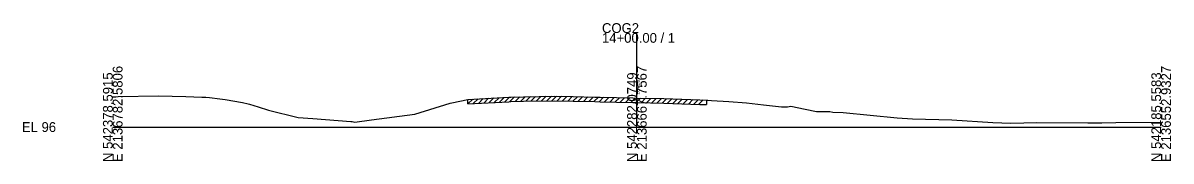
# Model space of a CAD drawing. Extents: x -13397 to 2303, y -10 to 39059.
# Drawn here: x -25.7 to 302.8, y 7990.3 to 8029.7 of the extents above; entities that cross this region are included whole.
import ezdxf

# ---------------------------------------------------------------- set-up
doc = ezdxf.new("R2010")
doc.units = 0
for name, color, linetype in [('RD_GPK_XS_Cell', 7, 'Continuous'), ('RD_XS_ExGround', 7, 'Continuous'), ('RD_XS_ExPaveRet', 7, 'Continuous'), ('RD_XS_TX_Elev_EX', 7, 'Continuous')]:
    doc.layers.add(name, color=color, linetype=linetype)

msp = doc.modelspace()

# ---------------------------------------------------------------- linework, layer by layer
at = {"layer": 'RD_GPK_XS_Cell'}
for p, q in [((150, 8000), (150, 8026.87)), ((0, 8000), (150, 8000)), ((150, 8000), (300, 8000))]:
    msp.add_line(p, q, dxfattribs=at)
at = {"layer": 'RD_XS_ExGround'}
for p, q in [((0, 8008.64), (0.86, 8008.67)), ((0.86, 8008.67), (1.51, 8008.68)), ((1.51, 8008.68), (13.13, 8008.96)), ((13.13, 8008.96), (20.96, 8008.7)), ((20.96, 8008.7), (25.51, 8008.54)), ((25.51, 8008.54), (26.68, 8008.5)), ((26.68, 8008.5), (27.7, 8008.46)), ((27.7, 8008.46), (30.66, 8008.02)), ((30.66, 8008.02), (32.19, 8007.84)), ((32.19, 8007.84), (37.13, 8007.03)), ((37.13, 8007.03), (38.78, 8006.62)), ((38.78, 8006.62), (39.1, 8006.5)), ((39.1, 8006.5), (41.59, 8005.73)), ((86.49, 8003.68), (96.57, 8006.78)), ((96.57, 8006.78), (97.08, 8006.91)), ((97.08, 8006.91), (101.65, 8007.91)), ((101.65, 8007.91), (113.36, 8008.55)), ((113.36, 8008.55), (113.91, 8008.58)), ((113.91, 8008.58), (117.5, 8008.65)), ((117.5, 8008.65), (126.4, 8008.83)), ((126.4, 8008.83), (131.72, 8008.7)), ((131.72, 8008.7), (137.99, 8008.56)), ((137.99, 8008.56), (139.49, 8008.51)), ((139.49, 8008.51), (148.84, 8008.3)), ((148.84, 8008.3), (150, 8008.28)), ((150, 8008.28), (157.72, 8008.11)), ((157.72, 8008.11), (168.02, 8007.78)), ((168.02, 8007.78), (169.9, 8007.71)), ((169.9, 8007.71), (170.3, 8007.7)), ((170.3, 8007.7), (171.37, 8007.61)), ((171.37, 8007.61), (176.34, 8007.27)), ((176.34, 8007.27), (181.37, 8006.96)), ((181.37, 8006.96), (186.19, 8006.39)), ((186.19, 8006.39), (191.37, 8005.78)), ((41.59, 8005.73), (44.61, 8004.79)), ((44.61, 8004.79), (53.09, 8002.77)), ((74.02, 8002.1), (86.49, 8003.68)), ((191.37, 8005.78), (193.05, 8005.81)), ((193.05, 8005.81), (194.03, 8005.94)), ((194.03, 8005.94), (198.12, 8005.09)), ((198.12, 8005.09), (201.38, 8004.4)), ((201.38, 8004.4), (203.09, 8004.48)), ((203.09, 8004.48), (205.16, 8004.4)), ((205.16, 8004.4), (206.06, 8004.25)), ((206.06, 8004.25), (209, 8004.13)), ((209, 8004.13), (224.45, 8002.59)), ((53.09, 8002.77), (57.25, 8002.46)), ((57.25, 8002.46), (68.14, 8001.62)), ((68.14, 8001.62), (68.5, 8001.56)), ((68.5, 8001.56), (69.28, 8001.44)), ((69.28, 8001.44), (74.02, 8002.1)), ((224.45, 8002.59), (228.85, 8002.36)), ((228.85, 8002.36), (240.11, 8002.07)), ((240.11, 8002.07), (251.86, 8001.32)), ((251.86, 8001.32), (254.45, 8001.18)), ((254.45, 8001.18), (257.01, 8001.15)), ((257.01, 8001.15), (264.45, 8001.28)), ((264.45, 8001.28), (279.02, 8001.19)), ((279.02, 8001.19), (283.08, 8001.21)), ((283.08, 8001.21), (287, 8001.27)), ((287, 8001.27), (300, 8001.41))]:
    msp.add_line(p, q, dxfattribs=at)
at = {"layer": 'RD_XS_ExPaveRet'}
for p, q in [((101.65, 8006.61), (103.03, 8007.98)), ((101.65, 8006.61), (101.65, 8007.91)), ((101.65, 8006.61), (113.36, 8007.25)), ((103.16, 8006.69), (104.53, 8008.07)), ((104.66, 8006.77), (106.03, 8008.15)), ((106.16, 8006.85), (107.54, 8008.23)), ((107.66, 8006.94), (109.04, 8008.31)), ((109.16, 8007.02), (110.54, 8008.39)), ((110.66, 8007.1), (112.04, 8008.47)), ((112.17, 8007.18), (113.54, 8008.56)), ((113.36, 8007.25), (113.91, 8007.28)), ((113.67, 8007.27), (115.01, 8008.6)), ((113.91, 8007.28), (117.5, 8007.35)), ((115.17, 8007.3), (116.5, 8008.63)), ((116.67, 8007.33), (118, 8008.66)), ((117.5, 8007.35), (126.4, 8007.53)), ((118.17, 8007.36), (119.5, 8008.69)), ((119.68, 8007.39), (121, 8008.72)), ((121.18, 8007.42), (122.51, 8008.75)), ((122.68, 8007.45), (124.01, 8008.78)), ((124.18, 8007.48), (125.51, 8008.81)), ((125.68, 8007.51), (126.99, 8008.81)), ((126.4, 8007.53), (131.72, 8007.4)), ((127.19, 8007.51), (128.46, 8008.78)), ((128.69, 8007.47), (129.96, 8008.74)), ((130.19, 8007.44), (131.46, 8008.71)), ((131.69, 8007.4), (132.96, 8008.67)), ((131.72, 8007.4), (137.99, 8007.26)), ((133.19, 8007.37), (134.47, 8008.64)), ((134.7, 8007.33), (135.97, 8008.6)), ((136.2, 8007.3), (137.47, 8008.57)), ((137.7, 8007.26), (138.97, 8008.53)), ((137.99, 8007.26), (139.49, 8007.21)), ((139.2, 8007.22), (140.47, 8008.49)), ((139.49, 8007.21), (148.84, 8007)), ((140.7, 8007.19), (141.98, 8008.46)), ((142.21, 8007.15), (143.48, 8008.42)), ((143.71, 8007.12), (144.98, 8008.39)), ((145.21, 8007.08), (146.48, 8008.35)), ((146.71, 8007.05), (147.98, 8008.32)), ((148.21, 8007.02), (149.49, 8008.29)), ((148.84, 8007), (150, 8006.98)), ((149.71, 8006.98), (150.99, 8008.26)), ((150, 8006.98), (157.72, 8006.81)), ((151.22, 8006.95), (152.49, 8008.22)), ((152.72, 8006.92), (153.99, 8008.19)), ((154.22, 8006.89), (155.5, 8008.16)), ((155.72, 8006.86), (157, 8008.13)), ((157.22, 8006.83), (158.49, 8008.09)), ((157.72, 8006.81), (168.02, 8006.48)), ((158.73, 8006.78), (159.99, 8008.04)), ((160.23, 8006.73), (161.49, 8007.99)), ((161.73, 8006.68), (162.99, 8007.94)), ((163.23, 8006.63), (164.49, 8007.89)), ((164.73, 8006.58), (165.99, 8007.84)), ((166.24, 8006.53), (167.5, 8007.79)), ((167.74, 8006.49), (169, 8007.74)), ((168.02, 8006.48), (169.9, 8006.41)), ((169.9, 8007.71), (169.9, 8006.41))]:
    msp.add_line(p, q, dxfattribs=at)

# ---------------------------------------------------------------- texts
at = {"layer": 'RD_GPK_XS_Cell'}
for s, p in [('COG2', (140, 8026.87)), ('14+00.00 / 1', (140, 8024.07)), ('EL 96', (-26, 7998.6))]:
    msp.add_text(s, height=2.8, dxfattribs=at).set_placement(p)
for s, p in [('E 2136782.5806', (2.8, 7990)), ('E 2136667.7567', (152.8, 7990)), ('E 2136552.9327', (302.8, 7990)), ('N 542378.5915', (0, 7990)), ('N 542282.0749', (150, 7990)), ('N 542185.5583', (300, 7990))]:
    msp.add_text(s, height=2.8, rotation=90, dxfattribs=at).set_placement(p)
at = {"layer": 'RD_XS_TX_Elev_EX'}
msp.add_text('104.28', height=1, rotation=90, dxfattribs=at).set_placement((150.75, 8009.28))

doc.saveas('drawing.dxf')
